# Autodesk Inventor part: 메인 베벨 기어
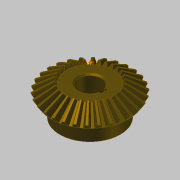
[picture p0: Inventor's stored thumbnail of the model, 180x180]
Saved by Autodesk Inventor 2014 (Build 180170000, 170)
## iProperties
Created: 2016-04
Part Number: 메인 베벨 기어
Material: 강철, 탄소
Document SubType Name: Modeling
Designer: mdu
Categories: <?xml version="1.0" encoding="UTF-16"?> <MemberInstance><Categories><FamilyTemplate><FamilyTemplateParameter ValueType="xs:double" Id="1" ObjectReferenceKey="da
Mass: 269.926 g
Surface Area: 108.837 cm^2
Volume: 34.2981 cm^3
Density: 7.87 g/cm^3
Appearance: Brindle
CustomPartVersion: 1
Author: mdu
Revision Number: 1
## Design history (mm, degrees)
node "맨 위 점"
node "메쉬 평면2"
sketch "톱니 본체 스케치"
  geometry: L1 (0, 0)-(28.669, -21.997); L2 (28.669, -21.997)-(31.109, -18.336); L3 (31.109, -18.336)-(0, 0); L4 (30, -20)-(0, 0); L5 (17.219, -13.212)-(18.685, -11.013); L6 (28.669, -21.997)-(17.219, -13.212); L7 (31.109, -18.336)-(18.685, -11.013); L8 (0, -39.387)-(0, 6.564) reference; L9 (0, -20)-(31.109, -20)
  constraints: 16 end point, 4 point on line, 3 perpendicular, 2 collinear, 1 horizontal alignment, 1 vertical alignment
  dimensions: "d0" = 60 diameter of L4.start L8 (= da_de); "d1" = 57.33744 diameter of L1.end L8 (= da_dfe); "d2" = 62.2188 diameter of L2.end L8 (= da_dae); "d3" = 14.4 distance between parallel lines of L2 L5 (= da_b); "d4" = 18.3359 vertical distance of L2.end L1.start (= da_ve)
revolve "톱니 본체" sketch "톱니 본체 스케치" stored, may be unused: angle "d5" = 90 deg
node "시작점"
node "톱니 평면"
sketch "시작 스케치"
  geometry: L1 (0, -23.505)-(0, 10.645) reference; L2 (-0.709, -2.928)-(0.709, -2.928); A1 r 19.188 centre (-19.457, -7.014) between (-0.709, -2.928) and (-3.232, 3.229); A2 r 19.188 centre (19.457, -7.014) between (3.232, 3.229) and (0.709, -2.928); A3 r 57.403 centre (0, -54.083) between (3.232, 3.229) and (-3.232, 3.229); 1 further point
  constraints: 6 point on circle, 3 centre point, 3 symmetric about line, 2 end point, 1 coincident, 1 perpendicular, 1 other
  dimensions: "d7" = 19.18795 radius of A1 (= fd_rr); "d8" = 19.45712 horizontal distance of point (0, -54.083) A1.centre (= fd_x); "d9" = 47.06905 vertical distance of point (0, -54.083) A1.centre (= fd_y); "d57" = 57.40327 radius of A3 (= 0.5 x fd_dva + 0.3 x da_he); "d58" = 51.15527 distance from line of A3.centre L2 (= 0.5 x fd_dva - 1.12 x da_he)
node "끝점"
  node "끝 평면"
sketch "3D 스케치 오른쪽"
  node "Helical Curve Right" dims "d65" = 229.90621 (computed from da_dm, da_delta, da_beta), "d66" = 31.5, "d67" = 60 (= da_de), "d68" = -9.82794 (= -da_delta), "d69" = 8.10972 (computed from fd_loft, da_delta)
node "끝 평면 오른쪽"
sketch "끝 스케치 오른쪽"
  geometry: L1 (0, -41.54)-(0, 13.178) reference; L2 (-0.422, -1.69)-(0.422, -1.69); A1 r 11.427 centre (-11.587, -4.123) between (-0.422, -1.69) and (-1.925, 1.977); A2 r 11.427 centre (11.587, -4.123) between (1.925, 1.977) and (0.422, -1.69); A3 r 34.184 centre (0, -32.153) between (1.925, 1.977) and (-1.925, 1.977); 1 further point
  constraints: 6 point on circle, 3 centre point, 3 symmetric about line, 2 end point, 1 coincident, 1 perpendicular, 1 other
  dimensions: "d70" = 11.58699 horizontal distance of A3.centre A1.centre (computed from fd_x, fd_ratio); "d71" = 28.03028 vertical distance of point (0, -32.153) A1.centre (computed from fd_y, fd_ratio); "d72" = 11.4267 radius of A1 (computed from fd_rr, fd_ratio); "d73" = 30.46369 distance from line of point (0, -32.153) L2 (computed from d58, fd_ratio); "d74" = 34.18446 radius of A3 (computed from d57, fd_ratio)
feature "로프트 오른쪽" sketch "끝 스케치 오른쪽" dims "d75" = 0, "d77" = 0, "d79" = 0, "d80" = 90 deg, "d85" = 20, "d92" = 90 deg, "d93" = 90 deg, "da_teethtype" = 0 [user parameter]
sketch "3D 스케치 왼쪽"
  node "Helical Curve Left" dims "d26" = 229.90621 (computed from da_dm, da_delta, da_beta), "d27" = 8.10972 (computed from fd_loft, da_delta), "d28" = 60 (= da_de), "d29" = -9.82794 (= -da_delta)
node "끝 평면 왼쪽"
sketch "끝 스케치 왼쪽" dims "d56" = 10.3728 (derived)
  geometry: L1 (0, -43.753)-(0, 15.405) reference; L2 (-0.422, -1.678)-(0.422, -1.678); A1 r 11.427 centre (-11.587, -4.111) between (-0.422, -1.678) and (-1.925, 1.988); A2 r 11.427 centre (11.587, -4.111) between (1.925, 1.988) and (0.422, -1.678); A3 r 34.184 centre (0, -32.142) between (1.925, 1.988) and (-1.925, 1.988); 2 further points; 1 other entity
  constraints: 6 point on circle, 3 centre point, 3 symmetric about line, 2 end point, 1 coincident, 2 other
  dimensions: "d30" = 11.4267 radius of A1 (computed from fd_rr, fd_ratio); "d31" = 11.58699 horizontal distance of point (0, -32.142) A1.centre (computed from fd_x, fd_ratio); "d32" = 28.03028 vertical distance of A1.centre point (0, -32.142) (computed from fd_y, fd_ratio); "d61" = 34.18446 radius of A3 (computed from d57, fd_ratio); "d62" = 30.46369 distance from line of point (0, -32.142) L2 (computed from d58, fd_ratio)
feature "로프트 왼쪽" sketch "끝 스케치 왼쪽" dims "d35" = 0, "d37" = 0, "d39" = 0, "d40" = 90 deg, "d84" = 10, "d90" = 90 deg, "d91" = 90 deg, "da_teethtype" = 0 [user parameter]
sketch "본체 스케치"
  geometry: L1 (0, -35.038)-(0, -19.531) reference; L2 (28.669, -21.997)-(17.219, -13.212) reference; L3 (17.219, -13.212)-(0, -13.212); L4 (28.669, -21.997)-(0, -21.997)
  constraints: 4 end point, 2 perpendicular, 2 point on line
revolve "본체 고정" sketch "본체 스케치" stored, may be unused: angle "d46" = 90 deg
feature "피치 지름" dims angle "d47" = 90 deg
sketch "스케치8"
  geometry: C1 r 22.5 at (0, 0); 1 further point
  constraints: 1 centre point, 1 coincident
  dimensions: "d94" = 45 diameter of C1
extrude "돌출1" join sketch "스케치8" distance "d95" = 13; taper "d96" = 0 deg
sketch "스케치9"
  geometry: 1 further point
hole "구멍1" sketch "스케치9" at (0, 0) diameter "d97" = 17; stored, may be unused: countersink angle "d101" = 90 deg, drill point angle "d103" = 118 deg; dims "d98" = 6, "d99" = 4, "d100" = 2, "d102" = 8
sketch "스케치10"
  geometry: L1 (8.124, 2.5)-(10.8, 2.5); L2 (10.8, 2.5)-(10.8, -2.5); L3 (10.8, -2.5)-(8.124, -2.5); A1 r 8.5 centre (0, 0) between (8.124, 2.5) and (8.124, -2.5) reference; 1 further point
  constraints: 6 end point, 2 parallel, 2 point on circle, 1 horizontal, 1 perpendicular
  dimensions: "d104" = 5 distance of L1.end L2.end; "d112" = 19.3 dimension on A1 L2
extrude "돌출2" cut sketch "스케치10" stored distance "d106" = 10; taper "d107" = 0 deg
chamfer "모따기1" distance "d108" = 1; stored, may be unused: second distance "d109" = 2, angle "d110" = 45 deg
fillet "모깎기1" dims "d111" = 2
body "Solid1"
feature "로프트" dims "d17" = 0, "d18" = 90 deg, "d19" = 0, "d20" = 90 deg, "d89" = 0, "da_teethtype" = 0 [user parameter]
pattern_circular "원형 패턴" dims angle "d22" = 360 deg, "d88" = 0, "da_teethtype" = 0 [user parameter]
pattern_circular "원형 패턴 오른쪽" dims angle "d82" = 360 deg, "da_teethtype" = 0 [user parameter]
pattern_circular "원형 패턴 왼쪽" dims angle "d42" = 360 deg, "da_teethtype" = 0 [user parameter]
sketch "끝 스케치"
  geometry: L1 (0, -15.359)-(0, 6.983) reference; L2 (-0.422, -1.69)-(0.422, -1.69); A1 r 11.427 centre (-11.587, -4.123) between (-0.422, -1.69) and (-1.925, 1.977); A2 r 11.427 centre (11.587, -4.123) between (1.925, 1.977) and (0.422, -1.69); A3 r 34.184 centre (0, -32.153) between (1.925, 1.977) and (-1.925, 1.977); 1 further point
  constraints: 6 point on circle, 3 centre point, 3 symmetric about line, 2 end point, 1 coincident, 1 other
  dimensions: "d12" = 11.4267 radius of A1 (computed from fd_rr, fd_ratio); "d15" = 11.58699 horizontal distance of A1.centre point (0, -32.153) (computed from fd_x, fd_ratio); "d16" = 28.03028 vertical distance of A1.centre point (0, -32.153) (computed from fd_y, fd_ratio); "d59" = 34.18446 radius of A3 (computed from d57, fd_ratio); "d60" = 30.46369 distance from line of A3.centre L2 (computed from d58, fd_ratio)
sketch "Sketch6"
  geometry: L1 (30, -20)-(0, 0) reference; L2 (0, -37.8)-(0, 6.3) reference
body "Srf1"
other parameters: "da_b" = 14.4 [user parameter; used in 2 equation terms], "da_de" = 60 [user parameter; used in 4 equation terms], "da_dae" = 62.2188 [user parameter; used in 2 equation terms], "da_dfe" = 57.33744 [user parameter; used in 1 equation term], "da_le" = 36.05551 [user parameter; used in 1 equation term], "da_omega" = 90 deg [user parameter; used in 1 equation term], "da_beta" = 0 [user parameter; used in 2 equation terms], "da_delta" = 9.82794 [user parameter; used in 8 equation terms], "da_alpha" = 20 deg [user parameter; used in 2 equation terms], "da_he" = 4.4 [user parameter; used in 4 equation terms], "da_ve" = 18.3359 [user parameter; used in 1 equation term], "fd_dv" = 108.16654 (computed from da_de, da_delta) [user parameter; used in 1 equation term], "fd_dva" = 112.16654 (computed from da_dae, da_delta) [user parameter; used in 3 equation terms], "fd_dvb" = 101.6433 (computed from fd_dv, da_alpha) [user parameter; used in 2 equation terms], "da_zv" = 540.83269 [user parameter; used in 1 equation term], "fd_loft" = 14.62 (= da_b + 0.05 x da_he) [user parameter; used in 4 equation terms], "fd_ratio" = 5.95514 (computed from da_le, fd_loft) [user parameter; used in 15 equation terms], "fd_rr" = 19.18795 (computed from fd_dd, fd_dvb) [user parameter; used in 6 equation terms], "fd_angle" = 0.29367 (computed from da_zv) [user parameter; used in 4 equation terms], "fd_x1" = 1.58802 (computed from da_dvw, fd_angle) [user parameter; used in 1 equation term], "fd_y1" = 54.05995 (computed from da_dvw, fd_angle) [user parameter; used in 1 equation term], "fd_x2" = 17.8691 (computed from fd_rr, fd_angle2, fd_angle) [user parameter; used in 1 equation term], "fd_y2" = 6.9909 (computed from fd_rr, fd_angle2, fd_angle) [user parameter; used in 1 equation term], "fd_x" = 19.45712 (= fd_x1 + fd_x2) [user parameter; used in 4 equation terms], "fd_y" = 47.06905 (= fd_y1 - fd_y2) [user parameter; used in 4 equation terms], "fd_angle2" = 3.43555 (computed from fd_dvb, fd_dd, da_alpha) [user parameter; used in 2 equation terms], "fd_dd" = 108.64654 (= fd_dva - 0.8 x da_he) [user parameter; used in 2 equation terms], "da_dvw" = 108.16654 [user parameter; used in 2 equation terms], "d11" = 14.62 (= fd_loft), "da_dm" = 48.01848 [user parameter; used in 2 equation terms], "da_x" = 0 [user parameter], "da_m" = 2 [user parameter], "d48" = 0, "d49" = 0, "d50" = 90 deg (= da_omega), "d51" = 6 deg (computed from da_z), "d52" = 0, "d53" = 0, "d54" = 0
